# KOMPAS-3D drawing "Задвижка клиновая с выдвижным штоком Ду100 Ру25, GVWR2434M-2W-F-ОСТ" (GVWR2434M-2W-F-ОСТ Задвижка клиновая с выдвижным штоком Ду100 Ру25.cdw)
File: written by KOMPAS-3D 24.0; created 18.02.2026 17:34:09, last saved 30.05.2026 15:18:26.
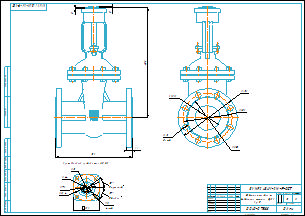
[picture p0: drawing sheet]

Document properties: Автор: R2D2; Форматы листов документа: A2; Полное имя файла: GVWR2434M-2W-F-ОСТ Задвижка клиновая с выдвижным штоком Ду100 Ру25.m3d; Масса: 32; Наименование: Задвижка клиновая с выдвижным штоком Ду100 Ру25; Количество листов документа: 1; Примечание: D040-07588

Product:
- Part/product: Задвижка клиновая с выдвижным штоком Ду100 Ру25  | designation GVWR2434M-2W-F-ОСТ
    Масса: 32
    Раздел спецификации: Прочие изделия
    Примечание: D040-07588

Views: Проекционный вид 3
Referenced files in E:\Работа\Зайцев\Для компаса\: чертеж DN.ru А3.cdt
Referenced files in E:\Работа\Зайцев\GVWR2434M-2W-F-ОСТ Задвижка клиновая с выдвижным штоком DN.ru Ду50-300 Ру25\исходные материалы\DN100\DN100\: GVWR2434M-2W-F-ОСТ Задвижка клиновая с выдвижным штоком Ду100 Ру25.m3d
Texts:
  Присоединение привода тип АК (А)
  чертеж DN.ru А3.cdt
  Задвижка клиновая с
  выдвижным штоком Ду100
  Ру25
  GVWR2434M-2W-F-ОСТ
  Задвижка клиновая с выдвижным штоком Ду100 Ру25
  GVWR2434M-2W-F-ОСТ Задвижка клиновая с выдвижным штоком Ду100 Ру25
Dimensions and other numbers on the sheet: 100; 5 кулачков; 5 впадин; 4 отв.; 104; 70; 44; 32; 1:2; 0; 1; 2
